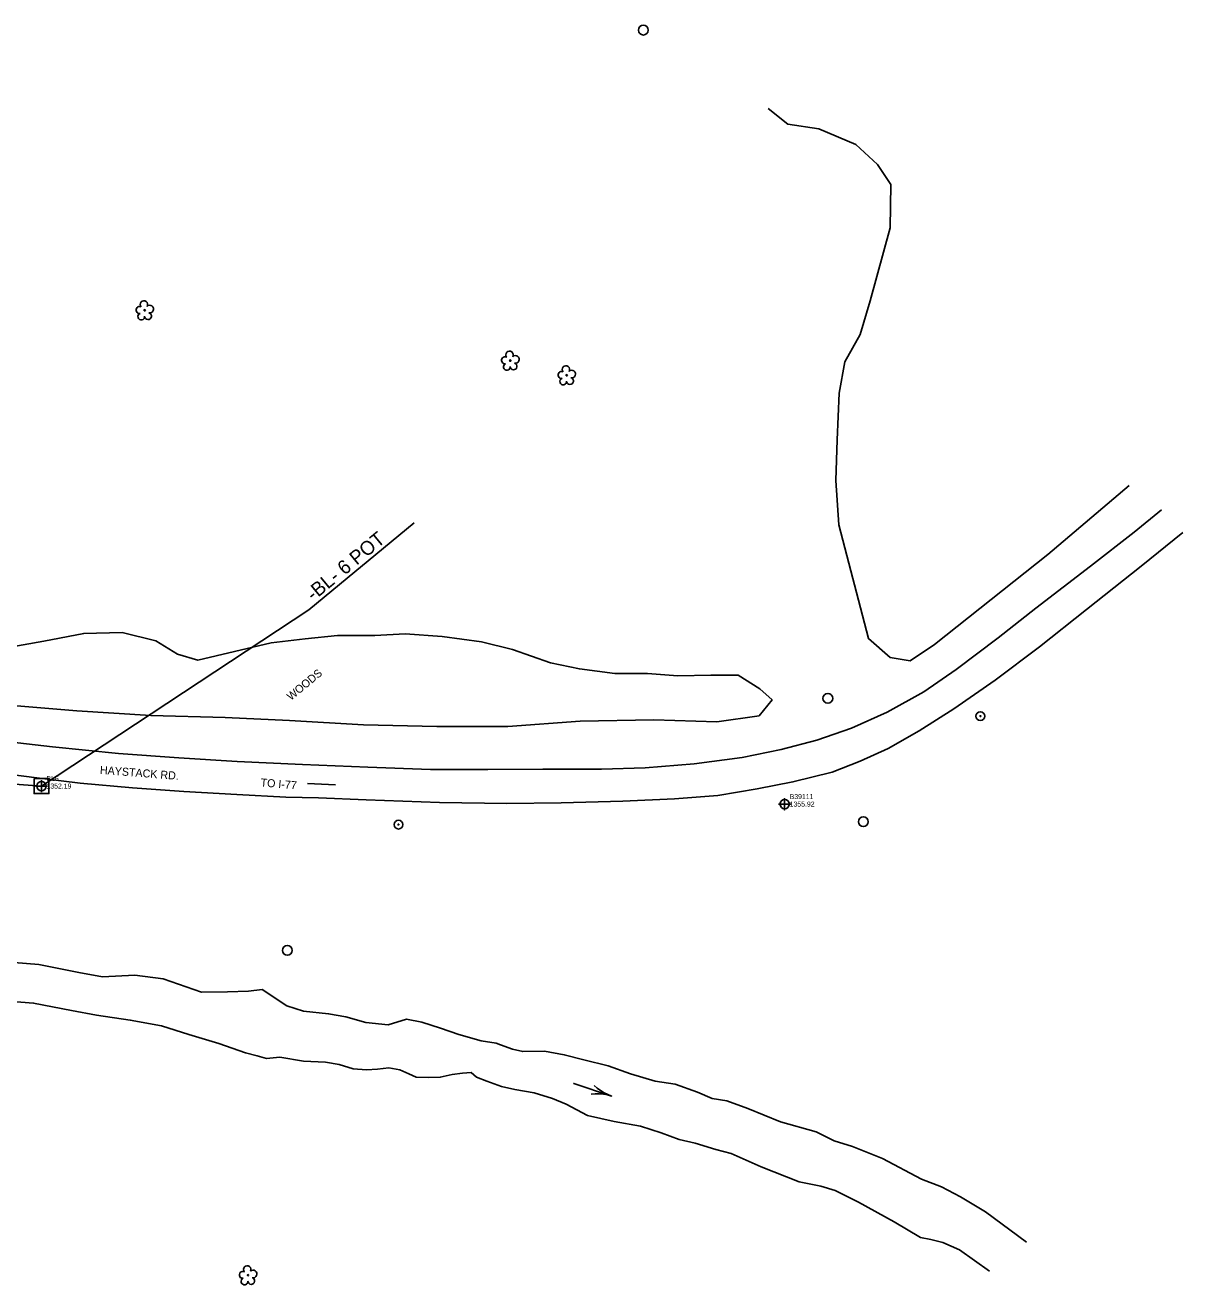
# Model space of a CAD drawing. Extents: x 1435573 to 1437263, y 981340 to 982884.
# Drawn here: x 1436684 to 1437263, y 982158 to 982788 of the extents above; entities that cross this region are included whole.
import ezdxf

# ---------------------------------------------------------------- set-up
doc = ezdxf.new("R2010")
doc.units = 0
for name, color, linetype in [('Cogo Default Point CELL', 7, 'Continuous'), ('COGO Default Point Elevation', 7, 'Continuous'), ('COGO Default Point Number', 7, 'Continuous'), ('CTL Supplemental Horizontal and Vertical CELL', 7, 'Continuous'), ('Default Symbol CELL', 7, 'Continuous'), ('Default Symbol Cogo Elevation', 7, 'Continuous'), ('Default Symbol Cogo Number', 7, 'Continuous'), ('Exist Horizontal Baseline Alignment', 7, 'Continuous'), ('Exist Horizontal Baseline Alignment Station Label', 7, 'Continuous'), ('Exist Hydro Jurisdictional Stream or Body of Water', 7, 'Continuous'), ('Exist Hydro River Flow Arrow CELL', 7, 'Continuous'), ('Exist Roads EOP', 7, 'Continuous'), ('Exist Roads EOP Leader', 7, 'Continuous'), ('Exist Roads EOP Text', 7, 'Continuous'), ('Exist Utilities Other Located Object CELL', 7, 'Continuous'), ('Exist Utilities Other Pole CELL', 7, 'Continuous'), ('Exist Vegetation Shrub Text', 7, 'Continuous'), ('Exist Vegetation Tree CELL', 7, 'Continuous'), ('Exist Vegetation Woods Line', 7, 'Continuous')]:
    doc.layers.add(name, color=color, linetype=linetype)

# ---------------------------------------------------------------- blocks, each defined once
blk = doc.blocks.new('CTL SUPPLEMENTAL HORIZONTAL AND VERTICAL')
at = {"layer": 'CTL Supplemental Horizontal and Vertical CELL'}
blk.add_line((0, 0), (0, 0), dxfattribs=at)
blk.add_lwpolyline([(-0.0735, 0.074), (0.07475, 0.074), (0.07475, -0.0745), (-0.0735, -0.0745)], close=True, dxfattribs=at)

msp = doc.modelspace()

# ---------------------------------------------------------------- linework, layer by layer
at = {"layer": 'Cogo Default Point CELL'}
for points in [[(1436692.1, 982410.77), (1436692.1, 982407.77)], [(1436689.1, 982407.77), (1436692.1, 982407.77)], [(1436692.1, 982407.77), (1436695.1, 982407.77)], [(1436692.1, 982407.77), (1436692.1, 982404.77)]]:
    msp.add_lwpolyline(points, dxfattribs=at)
msp.add_circle((1436692.1, 982407.77), 2.34, dxfattribs=at)
at = {"layer": 'Default Symbol CELL'}
msp.add_lwpolyline([(1437063.79, 982401.76), (1437063.79, 982395.76), (1437063.79, 982398.76), (1437066.79, 982398.76), (1437060.79, 982398.76)], dxfattribs=at)
msp.add_circle((1437063.79, 982398.76), 2.34, dxfattribs=at)
at = {"layer": 'Exist Horizontal Baseline Alignment'}
msp.add_line((1436220.79, 982442.59), (1436692.1, 982407.77), dxfattribs=at)
at = {"layer": 'Exist Horizontal Baseline Alignment Station Label'}
for p, q in [((1436825.81, 982495.83), (1436878.56, 982539.37)), ((1436692.1, 982407.77), (1436825.81, 982495.83))]:
    msp.add_line(p, q, dxfattribs=at)
at = {"layer": 'Exist Hydro Jurisdictional Stream or Body of Water'}
for points in [[(1436672.28, 982319.99), (1436690.8, 982318.55), (1436710.8, 982314.56), (1436722.65, 982312.42), (1436738.77, 982313.17), (1436752.98, 982311.32), (1436772.12, 982304.77), (1436785.08, 982304.83), (1436795.67, 982305.16), (1436802.51, 982306.14), (1436814.84, 982297.89), (1436823.19, 982295.24), (1436835.68, 982293.91), (1436844.34, 982292.43), (1436854.27, 982289.62), (1436865.46, 982288.39), (1436874.63, 982291.21), (1436882.28, 982289.8), (1436891.67, 982286.66), (1436900.88, 982283.59), (1436912, 982280.36), (1436919.58, 982279.22), (1436921.72, 982278.34), (1436927.67, 982276.24), (1436932.8, 982275.05), (1436943.66, 982275.16), (1436953.53, 982273.48), (1436963.43, 982270.9), (1436975.5, 982267.91), (1436986.73, 982263.88), (1436999.06, 982260.29), (1437009.1, 982258.75), (1437020.16, 982254.79), (1437027.55, 982251.59), (1437034.95, 982250.41), (1437045.38, 982246.53), (1437061.73, 982239.91), (1437079.62, 982234.95), (1437088.53, 982230.45), (1437097.67, 982227.62), (1437112.68, 982221.56), (1437132.28, 982211.26), (1437142.25, 982207.48), (1437151.75, 982202.44), (1437164.31, 982194.97), (1437184.82, 982179.76)], [(1436669.12, 982300.78), (1436688.14, 982299.3), (1436707.18, 982295.51), (1436719.53, 982293.27), (1436736.47, 982290.8), (1436752.2, 982287.89), (1436765.86, 982283.55), (1436780.77, 982279.11), (1436794.2, 982274.45), (1436799.96, 982272.95), (1436804.71, 982271.56), (1436811.33, 982272.16), (1436823.06, 982270.3), (1436834.14, 982269.7), (1436841, 982268.52), (1436848.02, 982266.47), (1436854.72, 982265.84), (1436860.12, 982266.24), (1436865.77, 982266.87), (1436871.38, 982265.86), (1436875.8, 982263.94), (1436879.52, 982262.23), (1436885.9, 982262.05), (1436891.51, 982262.17), (1436897.54, 982263.56), (1436902.71, 982264.26), (1436906.93, 982264.5), (1436909.7, 982262.31), (1436914.8, 982260.22), (1436922.23, 982257.59), (1436928.92, 982256.04), (1436938.57, 982254.33), (1436947.63, 982251.64), (1436954.54, 982248.72), (1436965.1, 982243.01), (1436978.59, 982240.02), (1436991.64, 982237.66), (1437002.07, 982234.39), (1437011.08, 982231.15), (1437019.11, 982229.17), (1437029.37, 982226.1), (1437036.97, 982224.15), (1437052, 982217.42), (1437070.97, 982209.83), (1437081.84, 982207.7), (1437089.06, 982205.55), (1437100.7, 982199.81), (1437118.55, 982189.98), (1437131.74, 982182.15), (1437136.96, 982181.06), (1437142.86, 982179.53), (1437151.28, 982175.94), (1437166.22, 982165.29)]]:
    msp.add_lwpolyline(points, dxfattribs=at)
at = {"layer": 'Exist Hydro River Flow Arrow CELL'}
msp.add_line((1436967.78, 982255.96), (1436967.78, 982255.96), dxfattribs=at)
msp.add_lwpolyline([(1436968.5, 982258.13), (1436970.04, 982256.78), (1436971.72, 982255.55), (1436973.5, 982254.46), (1436975.34, 982253.51), (1436977.26, 982252.79), (1436958.29, 982259.13), (1436977.26, 982252.79), (1436975.3, 982253.37), (1436973.25, 982253.72), (1436971.17, 982253.92), (1436969.09, 982253.94), (1436967.05, 982253.79)], dxfattribs=at)
at = {"layer": 'Exist Roads EOP'}
for points in [[(1437252.22, 982545.8), (1437238.52, 982534.7), (1437216.67, 982517.67), (1437189.41, 982496.63), (1437170.64, 982481.8), (1437149.58, 982466.03), (1437133.35, 982454.87), (1437115.06, 982444.77), (1437097.3, 982436.79), (1437079.91, 982430.71), (1437062, 982426), (1437042.61, 982422.06), (1437018.61, 982418.88), (1436993.97, 982416.96), (1436972.12, 982416.17), (1436942.88, 982416.21), (1436915.32, 982416.03), (1436886.61, 982416.08), (1436855.24, 982417.3), (1436822.62, 982418.63), (1436789.91, 982420.08), (1436760.73, 982421.8), (1436730.54, 982424.11), (1436697.66, 982427.3)], [(1436691.03, 982411.72), (1436711.48, 982409.15), (1436737.64, 982406.93), (1436763.27, 982405.02), (1436789.77, 982403.51), (1436814.28, 982402.17), (1436830.58, 982401.94), (1436854.54, 982400.88), (1436891.1, 982399.6), (1436924.78, 982399.09), (1436951.97, 982399.45), (1436982.78, 982400.19), (1437008.71, 982401.38), (1437030.34, 982403.08), (1437049.97, 982406.34), (1437067.94, 982409.88), (1437087.55, 982414.64), (1437101.54, 982420.23), (1437115.52, 982426.6), (1437131.14, 982435.36), (1437148.41, 982446.39), (1437169.04, 982460.68), (1437191.2, 982477.44), (1437214.71, 982496.04), (1437242.01, 982517.67), (1437262.92, 982534.48)], [(1436632.44, 982434.8), (1436697.66, 982427.3)], [(1436630.7, 982419.35), (1436691.03, 982411.72)]]:
    msp.add_lwpolyline(points, dxfattribs=at)
at = {"layer": 'Exist Roads EOP Leader'}
msp.add_lwpolyline([(1436839.08, 982408.38), (1436825.21, 982409.05)], dxfattribs=at)
at = {"layer": 'Exist Utilities Other Located Object CELL'}
for centre, radius in [((1437161.66, 982442.74), 2.18), ((1437161.66, 982442.74), 0.24), ((1436870.64, 982388.48), 2.18), ((1436870.64, 982388.48), 0.24)]:
    msp.add_circle(centre, radius, dxfattribs=at)
at = {"layer": 'Exist Utilities Other Pole CELL'}
for centre in [(1436993.11, 982785.69), (1437085.39, 982451.62), (1437103.12, 982389.95), (1436815.02, 982325.61)]:
    msp.add_circle(centre, 2.46, dxfattribs=at)
at = {"layer": 'Exist Vegetation Tree CELL'}
for p, q in [((1436743.72, 982645.63), (1436743.72, 982645.63)), ((1436926.56, 982620.47), (1436926.56, 982620.47)), ((1436954.77, 982613.16), (1436954.77, 982613.16)), ((1436795.37, 982163.24), (1436795.37, 982163.24))]:
    msp.add_line(p, q, dxfattribs=at)
for centre in [(1436743.72, 982645.63), (1436926.56, 982620.47), (1436954.77, 982613.16), (1436795.37, 982163.24)]:
    msp.add_circle(centre, 0.326, dxfattribs=at)
for centre, radius, start, end in [((1436743.33, 982648.51), 1.86, 330.16508, 219.71335), ((1436741.11, 982645.79), 1.73, 62.66361, 279.3457), ((1436742.01, 982642.51), 1.69, 111.56708, 6.23104), ((1436745.39, 982642.73), 1.7, 181.28216, 74.55999), ((1436746.27, 982646.22), 1.9, 257.1011, 134.19993), ((1436926.18, 982623.34), 1.86, 330.16508, 219.71335), ((1436923.96, 982620.62), 1.73, 62.66361, 279.3457), ((1436924.86, 982617.35), 1.69, 111.56708, 6.23104), ((1436928.24, 982617.57), 1.7, 181.28216, 74.55999), ((1436929.11, 982621.05), 1.9, 257.1011, 134.19993), ((1436952.16, 982613.31), 1.73, 62.66361, 279.3457), ((1436954.38, 982616.03), 1.86, 330.16508, 219.71335), ((1436956.44, 982610.26), 1.7, 181.28216, 74.55999), ((1436957.32, 982613.75), 1.9, 257.1011, 134.19993), ((1436953.06, 982610.04), 1.69, 111.56708, 6.23104), ((1436792.76, 982163.39), 1.73, 62.66361, 279.3457), ((1436794.98, 982166.11), 1.86, 330.16508, 219.71335), ((1436797.92, 982163.83), 1.9, 257.1011, 134.19993), ((1436793.66, 982160.12), 1.69, 111.56708, 6.23104), ((1436797.04, 982160.34), 1.7, 181.28216, 74.55999)]:
    msp.add_arc(centre, radius, start, end, dxfattribs=at)
at = {"layer": 'Exist Vegetation Woods Line'}
for points in [[(1437236.06, 982558.07), (1437195.33, 982523.53), (1437138.79, 982478.5), (1437126.55, 982470.43), (1437116.64, 982472.12), (1437105.8, 982481.47), (1437090.96, 982538.34), (1437089.45, 982560.6), (1437089.99, 982580.88), (1437090.97, 982604.12), (1437093.83, 982619.8), (1437101.6, 982633.55), (1437106.61, 982650.39), (1437116.63, 982686.93), (1437116.87, 982708.49), (1437110.18, 982718.5), (1437099.31, 982728.46), (1437080.87, 982736.35), (1437065.35, 982738.65), (1437055.51, 982746.56)], [(1436672.55, 982476.52), (1436693.3, 982480.24), (1436713.2, 982484.08), (1436732.38, 982484.6), (1436749.32, 982480.45), (1436760.2, 982473.69), (1436770.26, 982470.72), (1436807, 982479.34), (1436823.92, 982481.38), (1436840.22, 982483.1), (1436858.84, 982483.06), (1436873.93, 982483.85), (1436892.55, 982482.61), (1436912.11, 982479.84), (1436927.59, 982476.03), (1436946.7, 982469.38), (1436961.1, 982466.31), (1436978.88, 982464.06), (1436995.27, 982464.08), (1437010.28, 982462.81), (1437026.79, 982463.14), (1437040.53, 982463.18), (1437051.34, 982456.44), (1437057.47, 982450.93), (1437050.97, 982442.89), (1437029.85, 982439.92), (1436998.31, 982440.85), (1436961.46, 982440.28), (1436925.37, 982437.5), (1436889.85, 982437.48), (1436853.12, 982438.45), (1436816.06, 982440.55), (1436784, 982442.02), (1436746.8, 982443), (1436709.86, 982445.43), (1436673.85, 982448.35)]]:
    msp.add_lwpolyline(points, dxfattribs=at)

# ---------------------------------------------------------------- block references
at = {"layer": 'CTL Supplemental Horizontal and Vertical CELL', "xscale": 50, "yscale": 50}
msp.add_blockref('CTL SUPPLEMENTAL HORIZONTAL AND VERTICAL', (1436692.1, 982407.77), dxfattribs=at)

# ---------------------------------------------------------------- texts
at = {"layer": 'COGO Default Point Elevation'}
msp.add_text('1352.19', height=2.5, dxfattribs=at).set_placement((1436694.6, 982406.52))
at = {"layer": 'COGO Default Point Number'}
msp.add_text('BL6', height=2.5, dxfattribs=at).set_placement((1436694.6, 982410.27))
at = {"layer": 'Default Symbol Cogo Elevation'}
msp.add_text('1355.92', height=2.5, dxfattribs=at).set_placement((1437066.29, 982397.51))
at = {"layer": 'Default Symbol Cogo Number'}
msp.add_text('B39111', height=2.5, dxfattribs=at).set_placement((1437066.29, 982401.26))
at = {"layer": 'Exist Horizontal Baseline Alignment Station Label'}
msp.add_text('-BL- 6 POT  ', height=7, rotation=39.53989, dxfattribs=at).set_placement((1436828.06, 982500))
at = {"layer": 'Exist Roads EOP Text'}
for s, rotation, p in [('HAYSTACK RD.', 355.5352, (1436721.2, 982413.92)), ('TO I-77', 355.1455, (1436801.54, 982407.64))]:
    msp.add_text(s, height=4, rotation=rotation, dxfattribs=at).set_placement(p)
at = {"layer": 'Exist Vegetation Shrub Text'}
msp.add_text('WOODS', height=4, rotation=39.53989, dxfattribs=at).set_placement((1436816.85, 982450.34))

doc.saveas('drawing.dxf')
